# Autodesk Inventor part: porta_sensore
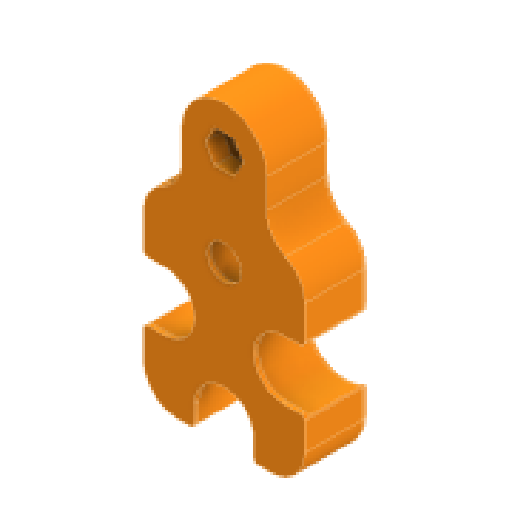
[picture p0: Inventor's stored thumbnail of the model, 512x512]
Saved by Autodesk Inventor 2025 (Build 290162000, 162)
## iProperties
Created: 2025-09
Part Number: porta_sensore
Material: Plastica ABS
Document SubType Name: Modeling
Designer: Ryzen5700u
Density: 1.06 g/cm^3
Appearance: Arancione
Author: Ryzen5700u
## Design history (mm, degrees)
sketch "Schizzo1"
  geometry: L1 (-10, -96)-(-10, 38) reference; L2 (9, -97)-(-9, -97) reference; L3 (10, 38)-(10, -96) reference; L4 (10, -97)-(-10, -97); L5 (-10, -97)-(-10, -77); L6 (-10, -77)-(10, -77); L7 (10, -77)-(10, -97); L8 (-10, 38)-(10, 38) reference; C1 r 2.25 at (0, -87) reference; A1 r 1 centre (-9, -96) between (-10, -96) and (-9, -97) reference; A2 r 1 centre (9, -96) between (9, -97) and (10, -96) reference; 7 further points
  constraints: 8 end point, 2 parallel, 1 horizontal, 1 perpendicular
  dimensions: "d0" = 20 distance of L5.end L6.end; "d1" = 20 distance of L4.end L5.end
extrude "Estrusione1" new body sketch "Schizzo1" distance "d2" = 40; taper "d3" = 0 deg
sketch "Schizzo2"
  geometry: L1 (1, 40)-(19, 40) reference; L2 (20, 40)-(0, 40); L3 (0, 40)-(0, 25); L4 (0, 25)-(20, 25); L5 (20, 25)-(20, 40); 5 further points
  constraints: 8 end point, 2 parallel, 1 horizontal, 1 perpendicular
  dimensions: "d4" = 20 distance of L4.end L3.end; "d5" = 15 distance of L3.end L2.end
extrude "Estrusione2" join sketch "Schizzo2" distance "d6" = 15; taper "d7" = 0 deg
sketch "Schizzo3"
  geometry: L1 (0, -15)-(20, -15) reference; L2 (10, -15)-(10, -78.397); L3 (20, -15)-(46.316, -15); L4 (0, -15)-(-26.316, -15); L5 (29, -15)-(-9, -15); L6 (-9, -15)-(-9, -60); L7 (-9, -60)-(29, -60); L8 (29, -60)-(29, -15); L9 (-9, -37.5)-(29, -37.5); L10 (-4, -28.5)-(-9, -28.5); L11 (24, -28.5)-(29, -28.5); L12 (-4, -46.5)-(-9, -46.5); L13 (1, -55)-(1, -60); L14 (19, -55)-(19, -60); L15 (24, -46.5)-(29, -46.5); C1 r 5.5 at (10, -22.614); A1 r 9 centre (-4, -37.5) between (-4, -28.5) and (-4, -46.5); A2 r 9 centre (24, -37.5) between (24, -28.5) and (24, -46.5); A3 r 9 centre (10, -55) between (1, -55) and (19, -55); 9 further points
  constraints: 28 end point, 13 point on line, 6 perpendicular, 6 point on circle, 4 centre point, 4 tangent, 3 midpoint, 2 horizontal, 2 parallel, 1 symmetric about line, 1 vertical, 1 other
  dimensions: "d28" = 45 distance of L6.end L5.end; "d29" = 38 distance of L6.end L7.end; "d30" = 18 diameter of A1; "d31" = 18 diameter of A2; "d32" = 5 distance from line of L6 A1.centre; "d33" = 5 distance from line of L8 A2.centre; "d34" = 11 diameter of C1; "d35" = 18 diameter of A3; "d36" = 5 distance from line of L7 A3.centre
extrude "Estrusione3" join sketch "Schizzo3" distance "d16" = 15; taper "d17" = 0 deg
sketch "Schizzo4"
  geometry: L1 (10, -77)-(-10, -77) reference; 2 further points
  dimensions: "d18" = 10 distance from line of L1 point (0, -87)
hole "Foro1" sketch "Schizzo4" at (0, -87) diameter "d19" = 4.5; stored, may be unused: countersink angle "d23" = 90 deg, drill point angle "d25" = 118 deg; dims "d20" = 6, "d21" = 8, "d22" = 20, "d24" = 8
sketch "Schizzo5"
  geometry: L1 (-10, -77)-(-10, -96) reference; L2 (-10, -112)-(-19, -112) reference; L3 (-19, -112)-(-19, -127.017) reference; L4 (-19, -141.983)-(-19, -157) reference; L5 (-19, -157)-(-7.483, -157) reference; L6 (7.483, -157)-(19, -157) reference; L7 (19, -157)-(19, -141.983) reference; L8 (19, -127.017)-(19, -112) reference; L9 (19, -112)-(10, -112) reference; L10 (10, -97)-(10, -112) reference; L11 (-14, -141.5)-(-19, -141.5); L12 (-19, -141.5)-(-19, -143.5); L13 (-14, -127.5)-(-19, -127.5); L14 (-19, -127.5)-(-19, -125.5); L15 (14, -127.5)-(19, -127.5); L16 (19, -127.5)-(19, -125.5); L17 (14, -141.5)-(19, -141.5); L18 (19, -143.5)-(19, -141.5); L19 (7, -152)-(7, -157); L20 (7, -157)-(9, -157); L21 (-7, -152)-(-7, -157); L22 (-7, -157)-(-9, -157); L23 (-9, -97)-(-10, -97) reference; L24 (-10, -97)-(-10, -112) reference; L25 (10, -97)-(9, -97) reference; L26 (10, -96)-(10, -77) reference; L27 (10, -77)-(-10, -77) reference; C1 r 5.5 at (0, -119.614) reference; C2 r 4 at (0, -119.614); A1 r 9 centre (-14, -134.5) between (-19, -141.983) and (-19, -127.017) reference; A2 r 9 centre (0, -152) between (7.483, -157) and (-7.483, -157) reference; A3 r 9 centre (14, -134.5) between (19, -127.017) and (19, -141.983) reference; A4 r 7 centre (0, -152) between (7, -152) and (-7, -152); A5 r 7 centre (-14, -134.5) between (-14, -141.5) and (-14, -127.5); A6 r 7 centre (14, -134.5) between (14, -127.5) and (14, -141.5); A7 r 1 centre (-9, -96) between (-10, -96) and (-9, -97) reference; A8 r 1 centre (9, -96) between (9, -97) and (10, -96) reference; 8 further points
  constraints: 24 end point, 8 point on line, 7 perpendicular, 6 point on circle, 4 centre point, 4 coincident, 4 tangent, 1 horizontal, 1 parallel
  dimensions: "d37" = 14 diameter of A4; "d38" = 14 diameter of A5; "d39" = 14 diameter of A6; "d40" = 8 diameter of C2
extrude "Estrusione4" join sketch "Schizzo5" distance "d41" = 1; taper "d42" = 0 deg
fillet "Raccordo3" dims "d43" = 8
fillet "Raccordo4" dims "d47" = 1
sketch "Schizzo6"
  geometry: L1 (4.4, -87)-(2.2, -90.811); L2 (2.2, -90.811)-(-2.2, -90.811); L3 (-2.2, -90.811)-(-4.4, -87); L4 (-4.4, -87)-(-2.2, -83.189); L5 (-2.2, -83.189)-(2.2, -83.189); L6 (2.2, -83.189)-(4.4, -87); C1 r 2.25 at (0, -87) reference; 2 further points
  constraints: 12 end point, 13 other
  dimensions: "d51" = 4.4 distance of L1.end L2.end
extrude "Estrusione5" cut sketch "Schizzo6" distance "d48" = 20; taper "d49" = 0 deg
fillet "Raccordo5" dims "d52" = 2
fillet "Raccordo6" dims "d53" = 5
sketch "Schizzo8"
  geometry: L1 (-10, -96)-(-10, -77) reference; L2 (9, -97)-(-9, -97) reference; L3 (10, -77)-(10, -96) reference; L4 (-10, -77)-(10, -77) reference; L5 (-10, -97)-(-10, -104) reference; L6 (10, -77)-(-10, -77); L7 (-10, -77)-(-10, -97); L8 (-10, -97)-(10, -97); L9 (10, -97)-(10, -77); C1 r 2.25 at (0, -87) reference; A1 r 1 centre (-9, -96) between (-10, -96) and (-9, -97) reference; A2 r 1 centre (9, -96) between (9, -97) and (10, -96) reference; 1 further point
  constraints: 8 end point, 2 parallel, 1 horizontal, 1 perpendicular
extrude "Estrusione7" cut sketch "Schizzo8" extent not by distance; stored distance "d58" = 0; taper "d59" = 0 deg
sketch "Schizzo9"
  geometry: L1 (20, -40)-(0, -40) reference; L2 (20, -25)-(20, -40) reference; L3 (0, -25)-(20, -25) reference; L4 (0, -40)-(0, -25) reference; 1 further point
extrude "Estrusione8" join sketch "Schizzo9" distance "d60" = 10; taper "d61" = 0 deg
sketch "Schizzo10"
  geometry: L1 (-10, 65)-(10, 65) reference; L2 (19, 25.5)-(19, 33.613) reference; L3 (10, 65)-(10, 48) reference; L4 (-10, 65)-(10, 65) reference; L5 (-10, 65)-(-10, 48) reference; L6 (-19, 33.613)-(-19, 25.5) reference; L7 (-19, 9.5)-(-19, 3) reference; L8 (-11, -5)-(-8, -5) reference; L9 (8, -5)-(11, -5) reference; L10 (19, 3)-(19, 9.5) reference; C1 r 10 at (0, 55); C2 r 5.5 at (0, 32.386) reference; A1 r 1 centre (18, 9.5) between (19, 9.5) and (18.894, 9.947) reference; A2 r 9 centre (14, 17.5) between (18.894, 25.053) and (18.894, 9.947) reference; A3 r 1 centre (18, 25.5) between (18.894, 25.053) and (19, 25.5) reference; A4 r 8 centre (11, 33.613) between (19, 33.613) and (14.5, 40.806) reference; A5 r 8 centre (18, 48) between (10, 48) and (14.5, 40.806) reference; A6 r 8 centre (-18, 48) between (-14.5, 40.806) and (-10, 48) reference; A7 r 8 centre (-11, 33.613) between (-14.5, 40.806) and (-19, 33.613) reference; A8 r 1 centre (-18, 25.5) between (-19, 25.5) and (-18.894, 25.053) reference; A9 r 9 centre (-14, 17.5) between (-18.894, 9.947) and (-18.894, 25.053) reference; A10 r 1 centre (-18, 9.5) between (-18.894, 9.947) and (-19, 9.5) reference; A11 r 8 centre (-11, 3) between (-19, 3) and (-11, -5) reference; A12 r 1 centre (-8, -4) between (-8, -5) and (-7.553, -4.894) reference; A13 r 9 centre (0, 0) between (7.553, -4.894) and (-7.553, -4.894) reference; A14 r 1 centre (8, -4) between (7.553, -4.894) and (8, -5) reference; A15 r 8 centre (11, 3) between (11, -5) and (19, 3) reference; 6 further points
  constraints: 1 centre point, 1 tangent
  dimensions: "d62" = 20 diameter of C1
extrude "Estrusione9" cut sketch "Schizzo10" extent not by distance; stored distance "d63" = 0; taper "d64" = 0 deg
sketch "Schizzo11"
  geometry: A1 r 10 centre (0, -97) between (10, -97) and (-10, -97) reference; 1 further point
hole "Foro2" sketch "Schizzo11" at (0, -97) diameter "d65" = 4.5; stored, may be unused: countersink angle "d69" = 90 deg, drill point angle "d71" = 118 deg; dims "d66" = 6, "d67" = 8, "d68" = 4.6, "d70" = 8
sketch "Schizzo12"
  geometry: L1 (4.5, -97)-(2.25, -100.897); L2 (2.25, -100.897)-(-2.25, -100.897); L3 (-2.25, -100.897)-(-4.5, -97); L4 (-4.5, -97)-(-2.25, -93.103); L5 (-2.25, -93.103)-(2.25, -93.103); L6 (2.25, -93.103)-(4.5, -97); C1 r 2.25 at (0, -97) reference; 2 further points
  constraints: 12 end point, 1 coincident, 13 other
  dimensions: "d72" = 4.5 distance of L1.end L2.end
extrude "Estrusione10" cut sketch "Schizzo12" distance "d73" = 4; taper "d74" = 0 deg
fillet "Raccordo9" dims "d75" = 1
node "Solido1"
node "Riferimento1"
node "Linea chiusa proiettata1"
node "Linea chiusa proiettata2"
node "Linea chiusa proiettata3"
node "Linea chiusa proiettata4"
